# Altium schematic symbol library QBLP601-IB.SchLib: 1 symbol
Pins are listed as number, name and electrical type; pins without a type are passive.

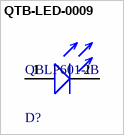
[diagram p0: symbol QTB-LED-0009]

## QTB-LED-0009
designator D?, comment QBLP601-IB
LED BLUE CLEAR 0603 SMD; Manufacturer: QT Brightek (QTB); Lens Size: 0.8mm; Luminous Intensity: 90mcd; Test Current: 20mA; Lens Color: Colorless; Lens Style: Flat; Forward Voltage: 3.2V; Wavelength - Dominant: 470nm
footprint QBLP601-IB-MFG
pins: 1 ANODE (+), 2 CATHODE (-)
